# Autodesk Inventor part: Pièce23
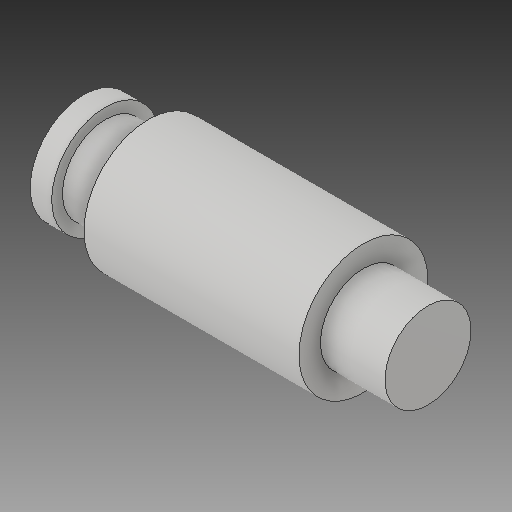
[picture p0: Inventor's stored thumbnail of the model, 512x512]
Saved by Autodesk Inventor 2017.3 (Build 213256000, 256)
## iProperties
Created: 2007-12
Part Number: Pièce23
Material: Générique
Document SubType Name: Modeling
Designer: ficho
Density: 1 g/cm^3
Appearance: Par défaut
Author: ficho
Sending System: SolidWorks 2009
Last Author: christophe
Last Saved: 2011-02-10
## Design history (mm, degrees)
feature "Révolution1"
node "Solide1"
